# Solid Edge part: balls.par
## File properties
Title: Bearing
Author: Abhinav Rai
Template: Normal.par
Last saved by: SOFT
Revision: 12
Application: Solid Edge
Accuracy: 0.99
Material: aluminum
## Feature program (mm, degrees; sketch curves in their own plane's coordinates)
sketch for "unnamed RevolvedProtrusion 1" plane through (0, 0, 0) normal (0, -1, 0) x-axis (1, 0, 0)
  arc centre (0, 0) radius 6.604 from (0, 6.604) to (0, -6.604) cw
  line (0, 6.604) -> (0, -6.604)
revolve "unnamed RevolvedProtrusion 1" add full turn 360 deg
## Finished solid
Body 1: solid body, 1 face, 0 edges, 0 vertices.
  Faces by surface: sphere 1
Spherical faces by radius (mm): R6.604 x1
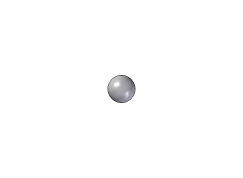
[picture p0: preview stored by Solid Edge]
